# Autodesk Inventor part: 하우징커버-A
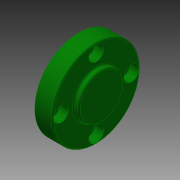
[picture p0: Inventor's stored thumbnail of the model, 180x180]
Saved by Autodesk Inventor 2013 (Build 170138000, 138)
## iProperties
Created: 2018-01
Part Number: 하우징커버-A
Material: 알루미늄 6061
Document SubType Name: Modeling
Designer: mduedu
Density: 2.71 g/cm^3
Mass: 18.1976 g
Surface Area: 30.9983 cm^2
Volume: 6.71499 cm^3
Author: mduedu
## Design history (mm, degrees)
sketch "스케치1"
  geometry: C1 r 17.5 at (0, 0); 1 further point
  constraints: 1 centre point, 1 coincident
  dimensions: "d0" = 35 diameter of C1
extrude "돌출1" new body sketch "스케치1" distance "d1" = 7; taper "d2" = 0 deg
sketch "스케치2"
  geometry: C1 r 9 at (0, 0); 1 further point
  constraints: 1 centre point, 1 coincident
  dimensions: "d3" = 18 diameter of C1
extrude "돌출2" join sketch "스케치2" distance "d4" = 2; taper "d5" = 0 deg
fillet "모깎기1" dims "d6" = 0.5
fillet "모깎기2" dims "d7" = 0.5
sketch "스케치3" dims "d8" = 25
  geometry: 6 further points
  constraints: 2 vertical alignment, 1 coincident, 7 other
  dimensions: "d11" = 360 deg dimension on point (0, 0) point (0, 12.5) (derived)
sketch "스케치4"
  geometry: C1 r 17.5 at (0, 0) reference; A1 r 14 centre (0, 0) between (0, 14) and (14, 0); 2 further points
  constraints: 4 point on circle, 2 horizontal alignment, 2 vertical alignment, 1 centre point, 1 coincident
  dimensions: "d22" = 28 diameter of A1
hole "구멍1" sketch "스케치4" at (-14, 0), (0, -14), (14, 0), (0, 14) diameter "d13" = 3.4; stored, may be unused: countersink angle "d17" = 90 deg, drill point angle "d19" = 0 deg; dims "d14" = 6, "d15" = 6, "d16" = 3.5, "d18" = 8
node "솔리드1"
